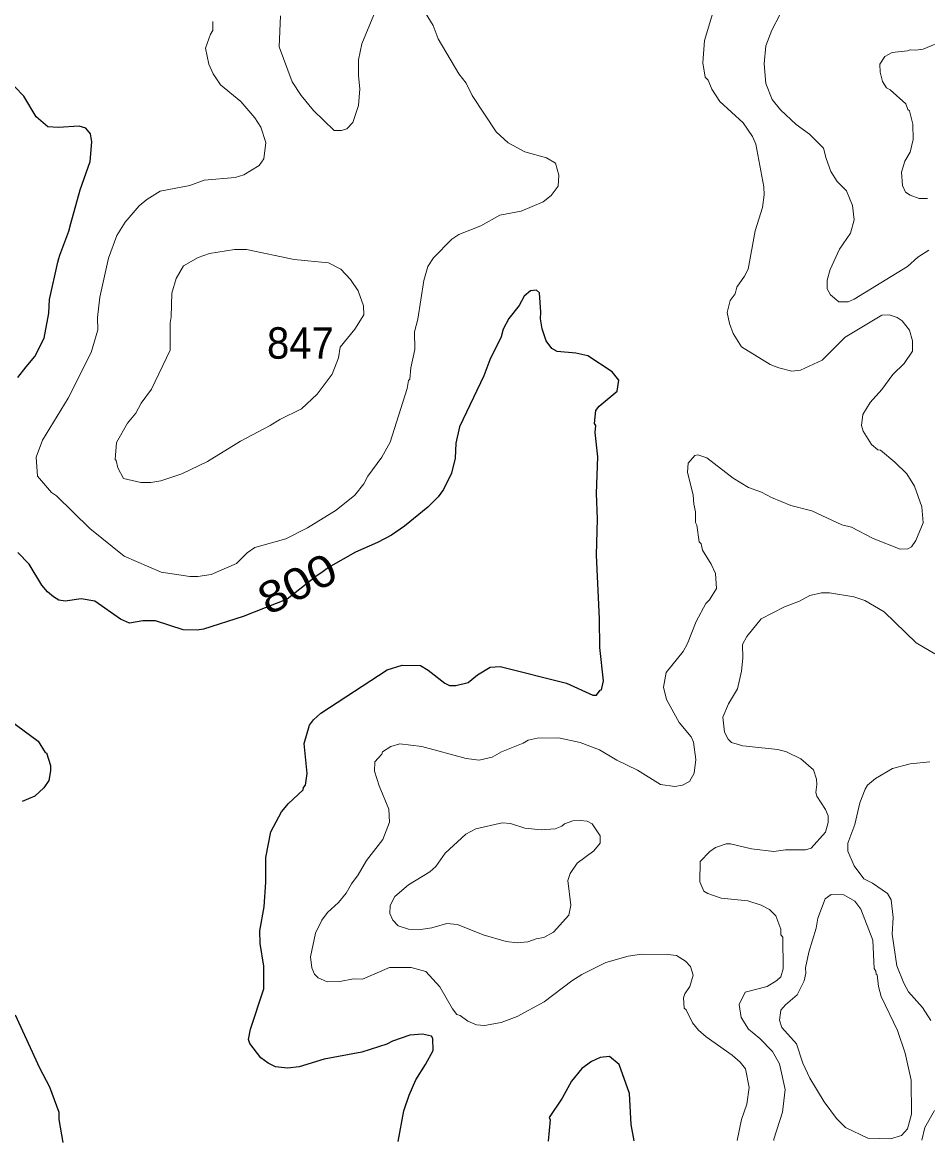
# Model space of a CAD drawing. Extents: x 447.8 to 473.9, y 7733.1 to 7760.8.
# Drawn here: x 449.088 to 451.388, y 7733.083 to 7735.931 of the extents above; entities that cross this region are included whole.
import ezdxf
from ezdxf.enums import TextEntityAlignment as Align

# ---------------------------------------------------------------- set-up
doc = ezdxf.new("R2010")
doc.units = 0
doc.header["$LTSCALE"] = 0.032
doc.layers.add('1', color=7, linetype='Continuous', lineweight=25)
doc.layers.add('2', color=7, linetype='Continuous', lineweight=13)
doc.layers.add('21', color=7, linetype='Continuous')
doc.layers.add('61', color=7, linetype='Continuous')

msp = doc.modelspace()

# ---------------------------------------------------------------- linework, layer by layer
at = {"layer": '1'}
for points in [[(449.0757, 7735.0278), (449.0972, 7735.0547), (449.1188, 7735.0816), (449.1428, 7735.1277), (449.1548, 7735.1911), (449.1569, 7735.2263), (449.1778, 7735.3208), (449.1798, 7735.3301), (449.183, 7735.3388), (449.2054, 7735.4003), (449.2105, 7735.4191), (449.234, 7735.5054), (449.26, 7735.5774), (449.2639, 7735.6267), (449.2605, 7735.6474), (449.2491, 7735.6617), (449.2318, 7735.6672), (449.1781, 7735.6633), (449.1521, 7735.6655), (449.1229, 7735.6909), (449.0913, 7735.7436), (449.0685, 7735.7667)], [(450.0428, 7733.0853), (450.0571, 7733.1639), (450.0702, 7733.2036), (450.0873, 7733.2427), (450.1122, 7733.2812), (450.1311, 7733.3171), (450.1304, 7733.3473), (450.1271, 7733.353), (450.104, 7733.3586), (450.0723, 7733.3563), (450.0282, 7733.3407), (450.0135, 7733.3328), (449.9504, 7733.313), (449.8547, 7733.2947), (449.7906, 7733.2752), (449.7609, 7733.272), (449.731, 7733.2755), (449.7121, 7733.2849), (449.6933, 7733.2987), (449.6656, 7733.335), (449.6625, 7733.3447), (449.6676, 7733.371), (449.7015, 7733.4733), (449.7007, 7733.5314), (449.6919, 7733.5891), (449.6912, 7733.6211), (449.7016, 7733.6826), (449.7064, 7733.7451), (449.7064, 7733.808), (449.7185, 7733.8725), (449.7458, 7733.924), (449.7642, 7733.9447), (449.8013, 7733.9794), (449.8022, 7733.9855), (449.8074, 7733.9915), (449.8114, 7734.0213), (449.8034, 7734.0974), (449.8173, 7734.1443), (449.8275, 7734.1579), (449.8461, 7734.1748), (450.0141, 7734.2847), (450.0527, 7734.2965), (450.099, 7734.2956), (450.1187, 7734.2842), (450.161, 7734.2507), (450.1733, 7734.2445), (450.1893, 7734.2445), (450.2202, 7734.2525), (450.2437, 7734.2718), (450.2761, 7734.2915), (450.3015, 7734.2933), (450.4699, 7734.2507), (450.5372, 7734.2204), (450.5463, 7734.2205), (450.5557, 7734.2327), (450.5591, 7734.2335), (450.564, 7734.2569), (450.5545, 7734.3419), (450.5544, 7734.4147), (450.5464, 7734.5762), (450.5488, 7734.6689), (450.5464, 7734.7333), (450.5496, 7734.8261), (450.5433, 7734.8885), (450.5449, 7734.906), (450.5417, 7734.9109), (450.5449, 7734.9438), (450.5531, 7734.9549), (450.5993, 7734.9935), (450.6032, 7735.0211), (450.5865, 7735.0427), (450.524, 7735.0828), (450.4938, 7735.09), (450.4464, 7735.0939), (450.4332, 7735.1017), (450.4183, 7735.1214), (450.4082, 7735.1515), (450.4039, 7735.1769), (450.4053, 7735.1939), (450.4012, 7735.243), (450.3943, 7735.2496), (450.3784, 7735.2487), (450.363, 7735.2351), (450.3498, 7735.2108), (450.3235, 7735.1779), (450.3095, 7735.151), (450.3043, 7735.131), (450.2754, 7735.0729), (450.26, 7735.0322), (450.198, 7734.9026), (450.1889, 7734.8613), (450.1873, 7734.8232), (450.1777, 7734.7846), (450.1577, 7734.743), (450.1438, 7734.7243)], [(450.1438, 7734.7243), (450.1182, 7734.6987), (450.0588, 7734.6498), (450.0257, 7734.6269), (449.9898, 7734.6082), (449.9337, 7734.5841)], [(449.9337, 7734.5841), (449.8654, 7734.5452), (449.8489, 7734.5326), (449.8365, 7734.5247), (449.7606, 7734.4641), (449.6485, 7734.4205), (449.5481, 7734.3879), (449.532, 7734.3855), (449.4961, 7734.3863), (449.4258, 7734.4095), (449.3938, 7734.4095), (449.3598, 7734.4033), (449.337, 7734.4132), (449.2716, 7734.4593), (449.237, 7734.4656), (449.1967, 7734.459), (449.1802, 7734.4619), (449.1663, 7734.4702), (449.1518, 7734.4829), (449.1367, 7734.5001), (449.1049, 7734.5532), (449.0761, 7734.583)], [(449.0371, 7734.1703), (449.1278, 7734.1031), (449.1452, 7734.0748), (449.1486, 7734.074), (449.1587, 7734.0411), (449.1594, 7734.0277), (449.155, 7734.0036), (449.1423, 7733.985), (449.1194, 7733.9635), (449.0867, 7733.9501)], [(449.0689, 7733.4077), (449.131, 7733.2726), (449.1567, 7733.2245), (449.1805, 7733.1603), (449.1801, 7733.1417), (449.1901, 7733.0828)], [(450.6424, 7733.087), (450.6346, 7733.129), (450.6304, 7733.2079), (450.6042, 7733.2814), (450.5793, 7733.3016), (450.556, 7733.2993), (450.5334, 7733.2893), (450.5095, 7733.2712), (450.4825, 7733.2387), (450.4594, 7733.1961), (450.4265, 7733.1464), (450.4287, 7733.1407), (450.4238, 7733.0864)]]:
    msp.add_lwpolyline(points, dxfattribs=at)
at = {"layer": '2'}
for points in [[(449.1385, 7734.869), (449.123, 7734.8254), (449.126, 7734.777), (449.1613, 7734.7358), (449.1744, 7734.7267), (449.2593, 7734.6437), (449.3459, 7734.5735), (449.4399, 7734.5331), (449.5134, 7734.5218), (449.5336, 7734.5218), (449.5676, 7734.5275), (449.6315, 7734.5553), (449.6589, 7734.5824), (449.6784, 7734.5955), (449.7568, 7734.6182), (449.8122, 7734.646), (449.8849, 7734.6905), (449.9321, 7734.729), (449.9551, 7734.7577), (449.965, 7734.7772), (450.0009, 7734.8253), (450.0222, 7734.8632), (450.0655, 7734.9999), (450.0688, 7735.02), (450.0719, 7735.0239), (450.0749, 7735.0529), (450.0847, 7735.0989), (450.084, 7735.1441), (450.0928, 7735.1762), (450.1074, 7735.2742), (450.1182, 7735.3099), (450.1325, 7735.3323), (450.1791, 7735.38), (450.1967, 7735.3917), (450.2527, 7735.4138), (450.3005, 7735.4409), (450.3554, 7735.4507), (450.4112, 7735.4745), (450.4316, 7735.4906), (450.4487, 7735.5144), (450.4511, 7735.5423), (450.4419, 7735.5728), (450.4197, 7735.5861), (450.3647, 7735.6017), (450.3221, 7735.6242), (450.2915, 7735.6523), (450.2308, 7735.7447), (450.215, 7735.7764), (450.1966, 7735.8), (450.1442, 7735.889), (450.1311, 7735.9232), (450.1044, 7735.9672)], [(450.8445, 7735.9639), (450.8205, 7735.8849), (450.8167, 7735.8276), (450.8223, 7735.7912), (450.83, 7735.7835), (450.8397, 7735.7613), (450.8598, 7735.7296), (450.9189, 7735.6755), (450.9432, 7735.6407), (450.9512, 7735.6215), (450.9713, 7735.5125), (450.9721, 7735.4925), (450.9682, 7735.46), (450.9498, 7735.4009), (450.9316, 7735.3036), (450.9229, 7735.2852), (450.903, 7735.2574), (450.8989, 7735.2406), (450.8862, 7735.2236), (450.8784, 7735.1931), (450.8844, 7735.1651), (450.8941, 7735.1396), (450.9148, 7735.1058), (450.9876, 7735.0611), (451.0094, 7735.0526), (451.0427, 7735.0444)], [(451.0128, 7735.9515), (450.9917, 7735.9108), (450.9767, 7735.871), (450.9721, 7735.8256), (450.977, 7735.7751), (450.9931, 7735.7351), (451.0138, 7735.7081), (451.0535, 7735.6712), (451.0878, 7735.6469), (451.1235, 7735.611), (451.1296, 7735.5846), (451.1415, 7735.5518), (451.1578, 7735.5265), (451.1813, 7735.5029), (451.197, 7735.4655), (451.2012, 7735.4292), (451.1919, 7735.3953), (451.164, 7735.3545), (451.1402, 7735.3029), (451.1325, 7735.2755), (451.1329, 7735.2534), (451.1412, 7735.2383), (451.1624, 7735.2207), (451.1858, 7735.2207), (451.2012, 7735.2267), (451.3365, 7735.3101), (451.3627, 7735.3339), (451.3911, 7735.3513)], [(449.5717, 7735.933), (449.5717, 7735.91), (449.5654, 7735.9009), (449.5528, 7735.8649), (449.5611, 7735.8242), (449.5723, 7735.8), (449.5912, 7735.7721), (449.6429, 7735.7298), (449.6781, 7735.6883), (449.6935, 7735.6648), (449.7063, 7735.6257), (449.701, 7735.5837), (449.6889, 7735.5672), (449.65, 7735.5436), (449.6281, 7735.5366), (449.5497, 7735.5294), (449.513, 7735.5159), (449.4374, 7735.5014), (449.4042, 7735.4804), (449.3847, 7735.4642), (449.3484, 7735.4225), (449.3279, 7735.3887), (449.306, 7735.3311), (449.284, 7735.2323)], [(449.7432, 7735.9473), (449.7401, 7735.8685), (449.7732, 7735.7797), (449.7956, 7735.745), (449.8269, 7735.7066), (449.8802, 7735.6557), (449.8984, 7735.656), (449.9117, 7735.6599), (449.9276, 7735.6761), (449.942, 7735.7194), (449.9452, 7735.7619), (449.9413, 7735.7951), (449.942, 7735.836), (449.9505, 7735.8764), (449.9805, 7735.9496)], [(451.3878, 7735.4829), (451.3666, 7735.4831), (451.3435, 7735.4912), (451.332, 7735.4991), (451.3241, 7735.5161), (451.3217, 7735.5499), (451.3302, 7735.5776), (451.3431, 7735.6005), (451.3512, 7735.6327), (451.3503, 7735.6719), (451.3416, 7735.7062), (451.3371, 7735.7089), (451.3323, 7735.7236), (451.2927, 7735.7595), (451.283, 7735.7646), (451.2733, 7735.7808), (451.2671, 7735.804), (451.2663, 7735.8244), (451.2793, 7735.8437), (451.2981, 7735.8546), (451.3368, 7735.8581), (451.3436, 7735.8612), (451.3571, 7735.8598), (451.3766, 7735.8628), (451.4331, 7735.8868)], [(449.284, 7735.2323), (449.2784, 7735.1809), (449.279, 7735.1495), (449.2624, 7735.0911), (449.2038, 7734.9755), (449.1385, 7734.869)], [(451.29, 7735.187), (451.3108, 7735.1807), (451.3227, 7735.1722), (451.3415, 7735.1486), (451.3496, 7735.1213), (451.3496, 7735.0952), (451.3284, 7735.0637), (451.2997, 7735.0353), (451.2715, 7734.9974), (451.2418, 7734.9644), (451.2231, 7734.9342), (451.2198, 7734.9062), (451.2239, 7734.8914), (451.2454, 7734.8576), (451.2611, 7734.8437), (451.268, 7734.843), (451.3049, 7734.8127), (451.335, 7734.7833), (451.3543, 7734.7513), (451.3729, 7734.6994), (451.3768, 7734.6581), (451.3579, 7734.6138), (451.3467, 7734.5976), (451.3373, 7734.5924), (451.3179, 7734.5915), (451.2497, 7734.619), (451.1943, 7734.6477), (451.1701, 7734.6533), (451.0933, 7734.6893), (451.0403, 7734.7027), (450.9908, 7734.7228), (450.9659, 7734.7368), (450.9326, 7734.748), (450.8941, 7734.7721), (450.8265, 7734.8237), (450.8037, 7734.831), (450.7967, 7734.8296), (450.7791, 7734.81), (450.7775, 7734.7875), (450.7924, 7734.7292), (450.7934, 7734.7058), (450.7981, 7734.6868), (450.7982, 7734.6597), (450.8013, 7734.6529), (450.8073, 7734.6101), (450.8122, 7734.6052), (450.816, 7734.5892), (450.8376, 7734.5535), (450.8486, 7734.5293), (450.851, 7734.4916), (450.8336, 7734.4627), (450.8239, 7734.4536), (450.7994, 7734.4073), (450.778, 7734.3518), (450.7664, 7734.3315), (450.7237, 7734.2776), (450.7165, 7734.2407), (450.7245, 7734.2095), (450.7566, 7734.1512), (450.7867, 7734.1148), (450.7933, 7734.1006), (450.7989, 7734.0571), (450.7948, 7734.0221), (450.783, 7734.001), (450.7648, 7733.9913), (450.7455, 7733.988), (450.7091, 7733.9935), (450.6504, 7734.0294), (450.5985, 7734.0551), (450.5544, 7734.0817), (450.5052, 7734.0997), (450.4499, 7734.1122), (450.3959, 7734.1107), (450.3724, 7734.1059), (450.3598, 7734.0982), (450.3054, 7734.0765), (450.2816, 7734.0623), (450.2486, 7734.0553), (450.2153, 7734.0591), (450.1028, 7734.0897), (450.0463, 7734.0962), (450.0236, 7734.0896), (450.0028, 7734.0762), (450.0011, 7734.0703), (449.9833, 7734.0507), (449.9821, 7734.0267), (449.9941, 7733.9902), (450.019, 7733.9302), (450.0205, 7733.8978), (450.0039, 7733.8538), (449.9618, 7733.8001), (449.9412, 7733.7635), (449.9236, 7733.7406), (449.9102, 7733.7172), (449.8905, 7733.6935)], [(451.0427, 7735.0444), (451.0645, 7735.047), (451.1198, 7735.0722), (451.1784, 7735.1303), (451.2716, 7735.1865), (451.29, 7735.187)], [(451.4063, 7734.3258), (451.3591, 7734.353), (451.2772, 7734.4321), (451.2284, 7734.4612), (451.2002, 7734.4705), (451.1386, 7734.4809), (451.1181, 7734.4807), (451.0881, 7734.4735), (451.0623, 7734.4591), (451.024, 7734.4447), (450.9649, 7734.4142), (450.9287, 7734.3699), (450.9178, 7734.3489), (450.9184, 7734.3142), (450.9151, 7734.2812), (450.9047, 7734.2364), (450.8815, 7734.1979), (450.8671, 7734.1648), (450.872, 7734.1261), (450.881, 7734.1087), (450.8896, 7734.1003), (450.9184, 7734.0913), (451.0074, 7734.0818), (451.0295, 7734.0764), (451.0657, 7734.0588), (451.0974, 7734.0306), (451.1058, 7734.0069), (451.1067, 7733.9928), (451.1036, 7733.9731), (451.1062, 7733.9632), (451.1282, 7733.9295), (451.1348, 7733.9138), (451.1348, 7733.8966), (451.1285, 7733.8722), (451.0923, 7733.8317), (451.0771, 7733.8268), (451.0268, 7733.8275), (450.9966, 7733.8228), (450.9405, 7733.8293), (450.887, 7733.8427), (450.8757, 7733.8426), (450.8485, 7733.8327), (450.8345, 7733.8229), (450.8098, 7733.7976), (450.8094, 7733.7455), (450.8189, 7733.7222), (450.829, 7733.7162), (450.8633, 7733.7046), (450.9309, 7733.6978), (450.9646, 7733.6867), (450.9857, 7733.6753), (451.0017, 7733.6592), (451.0145, 7733.6256), (451.015, 7733.6109), (451.0195, 7733.6052)], [(451.396, 7733.3934), (451.3748, 7733.4261), (451.3394, 7733.4663), (451.3271, 7733.488), (451.3097, 7733.5323), (451.2976, 7733.6131), (451.3, 7733.655), (451.2951, 7733.7001), (451.2855, 7733.7161), (451.248, 7733.742), (451.2259, 7733.7536), (451.201, 7733.7868), (451.1852, 7733.8239), (451.1852, 7733.8441), (451.2025, 7733.8912), (451.2157, 7733.9462), (451.2287, 7733.9815), (451.2354, 7733.9914), (451.2553, 7734.0081), (451.2984, 7734.0336), (451.3436, 7734.0457), (451.3935, 7734.051)], [(449.8905, 7733.6935), (449.8628, 7733.668), (449.8484, 7733.6486), (449.8328, 7733.6153), (449.8195, 7733.5553), (449.8228, 7733.5272)], [(451.0195, 7733.6052), (451.021, 7733.5247), (451.0144, 7733.5046), (451.0047, 7733.4948), (450.9803, 7733.4795), (450.9239, 7733.465)], [(449.8228, 7733.5272), (449.8297, 7733.5112), (449.8393, 7733.5015), (449.862, 7733.4918), (449.8944, 7733.4924), (449.9292, 7733.4989), (449.9519, 7733.4983), (450.0207, 7733.5278), (450.0755, 7733.5278), (450.1131, 7733.5175), (450.1484, 7733.4787), (450.1806, 7733.4226), (450.1916, 7733.4083), (450.2002, 7733.4057), (450.2197, 7733.3914), (450.2412, 7733.3822), (450.2617, 7733.3803), (450.3038, 7733.3879), (450.3451, 7733.4038), (450.4132, 7733.4408), (450.4837, 7733.4939), (450.509, 7733.5098), (450.5699, 7733.5404), (450.627, 7733.5567), (450.661, 7733.5615), (450.728, 7733.5614), (450.7499, 7733.5582), (450.7723, 7733.544), (450.7851, 7733.5302), (450.7924, 7733.5085), (450.7838, 7733.48), (450.7711, 7733.4607), (450.7678, 7733.4508), (450.7695, 7733.4245), (450.7742, 7733.4202), (450.7906, 7733.3873), (450.8056, 7733.3687), (450.8254, 7733.3517), (450.8914, 7733.3055), (450.9113, 7733.2871), (450.9248, 7733.2701), (450.9343, 7733.223), (450.9282, 7733.1806), (450.9151, 7733.1414), (450.904, 7733.0878)], [(450.9239, 7733.465), (450.9088, 7733.4337), (450.9136, 7733.4007), (450.9327, 7733.3708), (450.9611, 7733.3472), (450.9935, 7733.3148), (451.0113, 7733.283), (451.0258, 7733.2178), (451.0193, 7733.16), (450.997, 7733.0916), (450.997, 7733.088)], [(451.373, 7733.0891), (451.3811, 7733.1209), (451.4054, 7733.1648)]]:
    msp.add_lwpolyline(points, dxfattribs=at)
for points in [[(449.9549, 7735.1875), (449.9542, 7735.2105), (449.9405, 7735.2485), (449.9212, 7735.2768), (449.8969, 7735.3035), (449.8651, 7735.3193), (449.7779, 7735.328), (449.657, 7735.353), (449.6267, 7735.3531), (449.5634, 7735.3432), (449.5346, 7735.3328), (449.4971, 7735.3116), (449.4787, 7735.28), (449.4677, 7735.2422), (449.4659, 7735.1822), (449.4628, 7735.1672), (449.4627, 7735.0977), (449.4156, 7734.9982), (449.3891, 7734.9629), (449.3761, 7734.9372), (449.3543, 7734.9121), (449.3264, 7734.8628), (449.3233, 7734.8195), (449.3262, 7734.8171), (449.3297, 7734.7979), (449.3448, 7734.7715), (449.3889, 7734.7607), (449.414, 7734.7607), (449.4391, 7734.7652), (449.4925, 7734.7828), (449.5579, 7734.8146), (449.6415, 7734.8664), (449.7173, 7734.9056), (449.7414, 7734.9212), (449.7972, 7734.9484), (449.8368, 7734.9856), (449.8747, 7735.0364), (449.8908, 7735.0783), (449.8952, 7735.105), (449.9327, 7735.1508)], [(450.3172, 7733.594), (450.3447, 7733.5904), (450.3723, 7733.5933), (450.3928, 7733.6008), (450.4129, 7733.6043), (450.4372, 7733.6181), (450.4757, 7733.6609), (450.4808, 7733.6864), (450.4736, 7733.7495), (450.4794, 7733.7672), (450.4975, 7733.7931), (450.5398, 7733.8249), (450.556, 7733.844), (450.556, 7733.8631), (450.5357, 7733.8936), (450.5226, 7733.8998), (450.5047, 7733.9021), (450.4862, 7733.9006), (450.4652, 7733.8933), (450.4587, 7733.8876), (450.4416, 7733.8804), (450.4061, 7733.878), (450.3647, 7733.8823), (450.3275, 7733.894), (450.3069, 7733.8956), (450.2399, 7733.8804), (450.2141, 7733.867), (450.1617, 7733.8187), (450.1382, 7733.7849), (450.1229, 7733.7709), (450.069, 7733.738), (450.0336, 7733.7084), (450.0224, 7733.6856), (450.0215, 7733.6652), (450.0288, 7733.6486), (450.0423, 7733.6335), (450.0691, 7733.6251), (450.0994, 7733.6248), (450.1283, 7733.6289), (450.1662, 7733.6399), (450.1931, 7733.6377), (450.2586, 7733.6109)], [(451.1252, 7733.1867), (451.0885, 7733.247), (451.0711, 7733.2847), (451.0547, 7733.3335), (451.017, 7733.375), (451.0115, 7733.3941), (451.0147, 7733.4194), (451.0267, 7733.4333), (451.0561, 7733.4581), (451.074, 7733.4944), (451.0787, 7733.5133), (451.0772, 7733.527), (451.0861, 7733.5671), (451.1043, 7733.6277), (451.1089, 7733.6538), (451.1276, 7733.7022), (451.1428, 7733.7137), (451.1746, 7733.7129), (451.2027, 7733.6963), (451.2184, 7733.6763), (451.2484, 7733.5973), (451.2519, 7733.525), (451.2566, 7733.5187), (451.2567, 7733.5113), (451.2598, 7733.5096), (451.2631, 7733.4798), (451.2695, 7733.4541), (451.3111, 7733.3674), (451.3311, 7733.3104), (451.3457, 7733.2418), (451.3472, 7733.1552), (451.3369, 7733.1177), (451.3211, 7733.1008), (451.2935, 7733.0926), (451.2358, 7733.0942), (451.1792, 7733.1211), (451.1562, 7733.1441)]]:
    msp.add_lwpolyline(points, close=True, dxfattribs=at)

# ---------------------------------------------------------------- texts
at = {"layer": '21', "width": 0.95}
msp.add_text('847', height=0.08, dxfattribs=at).set_placement((449.7092, 7735.0757))
at = {"layer": '61', "width": 1.15}
msp.add_text('800', height=0.08, rotation=26.565, dxfattribs=at).set_placement((449.8041, 7734.468), align=Align.CENTER)

doc.saveas('drawing.dxf')
